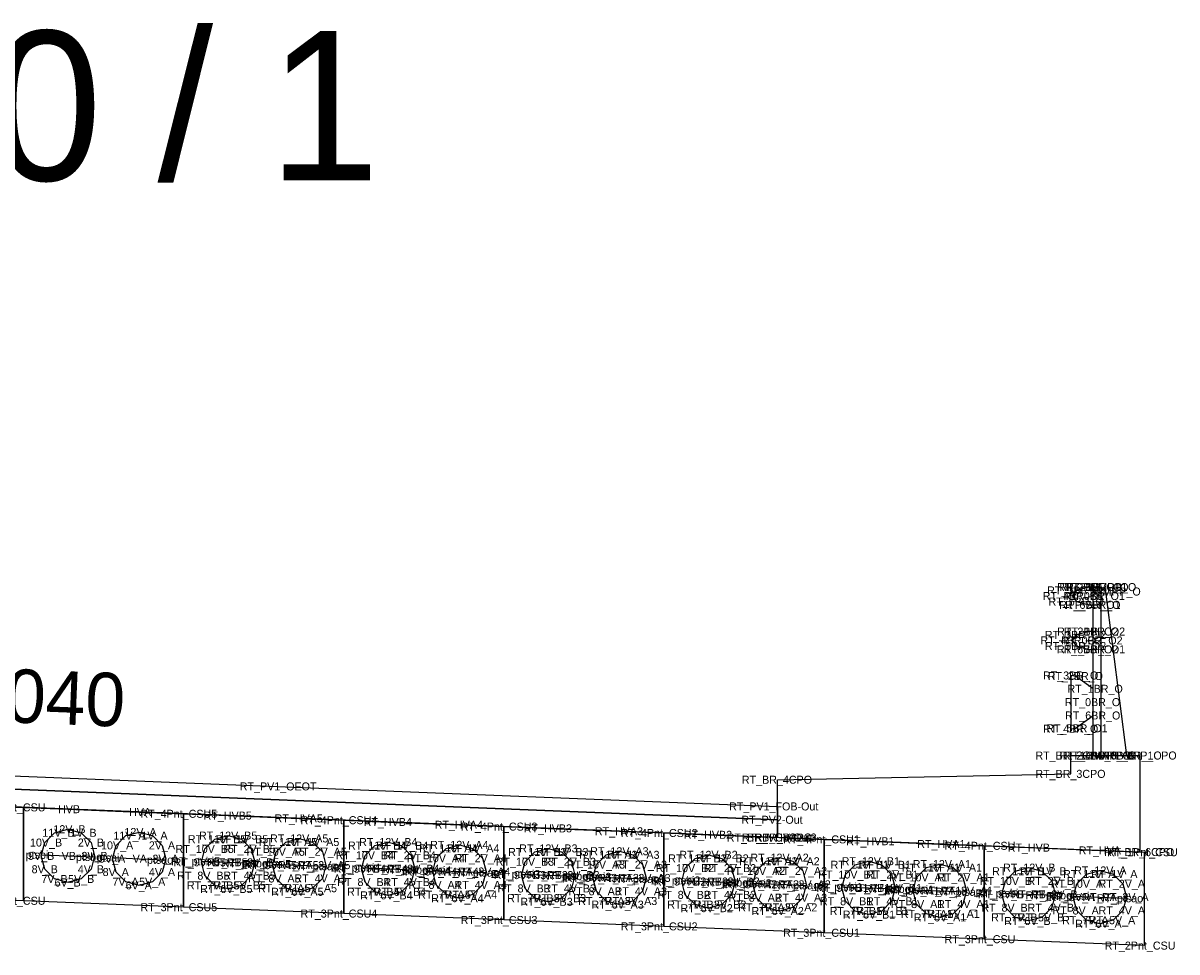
# Model space of a CAD drawing. Extents: x -26 to 1163, y -10 to 9537.
# Drawn here: x 84.24 to 105.86, y 6514.13 to 6531.53 of the extents above; entities that cross this region are included whole.
import ezdxf

# ---------------------------------------------------------------- set-up
doc = ezdxf.new("R2010")
doc.units = 0
for name, color, linetype in [('Exist Cross Section Cell', 7, 'Continuous'), ('Prop CMT Bridge Metal Rail', 7, 'Continuous'), ('Prop CMT Bridge Metal Rail Post', 7, 'Continuous'), ('Prop CMT Concrete Structures', 7, 'Continuous'), ('Prop CMT Corridor Surface Symbology Blue', 7, 'Continuous'), ('Prop CMT Pvmt Course 1', 7, 'Continuous'), ('Prop CMT Pvmt Course 2', 7, 'Continuous'), ('Prop XS SE Text', 7, 'Continuous'), ('Scratch_Level_0', 7, 'Continuous')]:
    doc.layers.add(name, color=color, linetype=linetype)

msp = doc.modelspace()

# ---------------------------------------------------------------- linework, layer by layer
at = {"layer": 'Prop CMT Bridge Metal Rail'}
for points in [[(104.293, 6520.965), (104.209, 6520.965), (103.98, 6520.902), (103.897, 6520.798)], [(104.293, 6520.798), (104.293, 6520.965)], [(103.897, 6520.798), (103.98, 6520.694), (104.209, 6520.632), (104.293, 6520.632)], [(104.293, 6520.632), (104.293, 6520.798)], [(104.293, 6520.132), (104.209, 6520.132), (103.98, 6520.069), (103.897, 6519.965)], [(103.897, 6519.965), (103.98, 6519.861), (104.209, 6519.798), (104.293, 6519.798)], [(104.293, 6519.965), (104.293, 6520.132)], [(104.293, 6519.798), (104.293, 6519.965)], [(104.293, 6519.059), (103.964, 6519.298), (103.876, 6519.309)], [(103.876, 6519.309), (103.876, 6518.309)], [(104.293, 6518.809), (104.293, 6519.059)], [(104.293, 6518.559), (104.293, 6518.809)], [(103.876, 6518.309), (103.964, 6518.319), (104.293, 6518.559)]]:
    msp.add_lwpolyline(points, dxfattribs=at)
at = {"layer": 'Prop CMT Bridge Metal Rail Post'}
for points in [[(104.293, 6517.809), (104.293, 6520.965)], [(104.293, 6520.965), (104.438, 6520.965)], [(104.438, 6520.965), (104.438, 6517.809)], [(104.438, 6520.965), (104.522, 6520.882), (104.918, 6517.809)]]:
    msp.add_lwpolyline(points, dxfattribs=at)
at = {"layer": 'Prop CMT Concrete Structures'}
for points in [[(98.375, 6516.272), (98.376, 6517.355), (103.875, 6517.465), (103.876, 6517.809), (105.166, 6517.809), (105.167, 6516)], [(81.25, 6516.957), (82.083, 6516.923), (83.417, 6516.87), (84.25, 6516.837)], [(84.25, 6516.837), (84.25, 6515.087)], [(84.25, 6516.837), (85.083, 6516.803), (86.417, 6516.75), (87.25, 6516.717)], [(84.25, 6515.087), (84.25, 6516.837)], [(87.25, 6516.717), (88.083, 6516.683), (89.417, 6516.63), (90.25, 6516.597)], [(87.25, 6514.967), (87.25, 6516.717)], [(87.25, 6516.717), (87.25, 6514.967)], [(90.25, 6516.597), (90.25, 6514.847)], [(90.25, 6516.597), (91.083, 6516.563), (92.417, 6516.51), (93.25, 6516.477)], [(90.25, 6514.847), (90.25, 6516.597)], [(93.25, 6516.477), (93.25, 6514.727)], [(93.25, 6516.477), (94.083, 6516.443), (95.417, 6516.39), (96.25, 6516.357)], [(93.25, 6514.727), (93.25, 6516.477)], [(84.583, 6515.928), (84.65, 6516.178), (84.833, 6516.361), (85.083, 6516.428)], [(85.083, 6516.428), (85.333, 6516.361), (85.516, 6516.178), (85.583, 6515.928)], [(85.917, 6515.875), (85.984, 6516.125), (86.167, 6516.308), (86.417, 6516.375)], [(86.417, 6516.375), (86.667, 6516.308), (86.85, 6516.125), (86.917, 6515.875)], [(87.583, 6515.808), (87.65, 6516.058), (87.833, 6516.241), (88.083, 6516.308)], [(88.083, 6516.308), (88.333, 6516.241), (88.516, 6516.058), (88.583, 6515.808)], [(96.25, 6516.357), (96.25, 6514.607)], [(96.25, 6516.357), (97.083, 6516.323), (98.417, 6516.27), (99.25, 6516.237)], [(96.25, 6514.607), (96.25, 6516.357)], [(105.167, 6516), (98.375, 6516.272)], [(88.917, 6515.755), (88.984, 6516.005), (89.167, 6516.188), (89.417, 6516.255)], [(89.417, 6516.255), (89.667, 6516.188), (89.85, 6516.005), (89.917, 6515.755)], [(90.583, 6515.688), (90.65, 6515.938), (90.833, 6516.121), (91.083, 6516.188)], [(91.083, 6516.188), (91.333, 6516.121), (91.516, 6515.938), (91.583, 6515.688)], [(91.917, 6515.635), (91.984, 6515.885), (92.167, 6516.068), (92.417, 6516.135)], [(92.417, 6516.135), (92.667, 6516.068), (92.85, 6515.885), (92.917, 6515.635)], [(93.583, 6515.568), (93.65, 6515.818), (93.833, 6516.001), (94.083, 6516.068)], [(94.083, 6516.068), (94.333, 6516.001), (94.516, 6515.818), (94.583, 6515.568)], [(99.25, 6516.237), (99.25, 6514.487)], [(99.25, 6516.237), (100.083, 6516.203), (101.417, 6516.15), (102.25, 6516.117)], [(99.25, 6514.487), (99.25, 6516.237)], [(102.25, 6516.117), (102.25, 6514.367)], [(102.25, 6516.117), (103.083, 6516.083), (104.417, 6516.03), (105.25, 6515.997)], [(102.25, 6514.367), (102.25, 6516.117)], [(85.583, 6515.928), (85.516, 6515.678), (85.333, 6515.495), (85.083, 6515.428), (84.833, 6515.495), (84.65, 6515.678), (84.583, 6515.928)], [(86.917, 6515.875), (86.85, 6515.625), (86.667, 6515.442), (86.417, 6515.375), (86.167, 6515.442), (85.984, 6515.625), (85.917, 6515.875)], [(94.917, 6515.515), (94.984, 6515.765), (95.167, 6515.948), (95.417, 6516.015)], [(95.417, 6516.015), (95.667, 6515.948), (95.85, 6515.765), (95.917, 6515.515)], [(96.583, 6515.448), (96.65, 6515.698), (96.833, 6515.881), (97.083, 6515.948)], [(97.083, 6515.948), (97.333, 6515.881), (97.516, 6515.698), (97.583, 6515.448)], [(97.917, 6515.395), (97.984, 6515.645), (98.167, 6515.828), (98.417, 6515.895)], [(98.417, 6515.895), (98.667, 6515.828), (98.85, 6515.645), (98.917, 6515.395)], [(99.583, 6515.328), (99.65, 6515.578), (99.833, 6515.761), (100.083, 6515.828)], [(100.083, 6515.828), (100.333, 6515.761), (100.516, 6515.578), (100.583, 6515.328)], [(105.25, 6515.997), (105.25, 6514.247)], [(88.583, 6515.808), (88.516, 6515.558), (88.333, 6515.375), (88.083, 6515.308), (87.833, 6515.375), (87.65, 6515.558), (87.583, 6515.808)], [(89.917, 6515.755), (89.85, 6515.505), (89.667, 6515.322), (89.417, 6515.255), (89.167, 6515.322), (88.984, 6515.505), (88.917, 6515.755)], [(91.583, 6515.688), (91.516, 6515.438), (91.333, 6515.255), (91.083, 6515.188), (90.833, 6515.255), (90.65, 6515.438), (90.583, 6515.688)], [(92.917, 6515.635), (92.85, 6515.385), (92.667, 6515.202), (92.417, 6515.135), (92.167, 6515.202), (91.984, 6515.385), (91.917, 6515.635)], [(100.917, 6515.275), (100.984, 6515.525), (101.167, 6515.708), (101.417, 6515.775)], [(101.417, 6515.775), (101.667, 6515.708), (101.85, 6515.525), (101.917, 6515.275)], [(102.583, 6515.208), (102.65, 6515.458), (102.833, 6515.641), (103.083, 6515.708)], [(103.083, 6515.708), (103.333, 6515.641), (103.516, 6515.458), (103.583, 6515.208)], [(103.917, 6515.155), (103.984, 6515.405), (104.167, 6515.588), (104.417, 6515.655)], [(104.417, 6515.655), (104.667, 6515.588), (104.85, 6515.405), (104.917, 6515.155)], [(94.583, 6515.568), (94.516, 6515.318), (94.333, 6515.135), (94.083, 6515.068), (93.833, 6515.135), (93.65, 6515.318), (93.583, 6515.568)], [(95.917, 6515.515), (95.85, 6515.265), (95.667, 6515.082), (95.417, 6515.015), (95.167, 6515.082), (94.984, 6515.265), (94.917, 6515.515)], [(97.583, 6515.448), (97.516, 6515.198), (97.333, 6515.015), (97.083, 6514.948), (96.833, 6515.015), (96.65, 6515.198), (96.583, 6515.448)], [(84.25, 6515.087), (81.25, 6515.207)], [(98.917, 6515.395), (98.85, 6515.145), (98.667, 6514.962), (98.417, 6514.895), (98.167, 6514.962), (97.984, 6515.145), (97.917, 6515.395)], [(100.583, 6515.328), (100.516, 6515.078), (100.333, 6514.895), (100.083, 6514.828), (99.833, 6514.895), (99.65, 6515.078), (99.583, 6515.328)], [(101.917, 6515.275), (101.85, 6515.025), (101.667, 6514.842), (101.417, 6514.775), (101.167, 6514.842), (100.984, 6515.025), (100.917, 6515.275)], [(103.583, 6515.208), (103.516, 6514.958), (103.333, 6514.775), (103.083, 6514.708), (102.833, 6514.775), (102.65, 6514.958), (102.583, 6515.208)], [(87.25, 6514.967), (84.25, 6515.087)], [(90.25, 6514.847), (87.25, 6514.967)], [(104.917, 6515.155), (104.85, 6514.905), (104.667, 6514.722), (104.417, 6514.655), (104.167, 6514.722), (103.984, 6514.905), (103.917, 6515.155)], [(93.25, 6514.727), (90.25, 6514.847)], [(96.25, 6514.607), (93.25, 6514.727)], [(99.25, 6514.487), (96.25, 6514.607)], [(102.25, 6514.367), (99.25, 6514.487)], [(105.25, 6514.247), (102.25, 6514.367)]]:
    msp.add_lwpolyline(points, dxfattribs=at)
at = {"layer": 'Prop CMT Corridor Surface Symbology Blue'}
for points in [[(84.593, 6515.948), (85.083, 6515.928), (85.573, 6515.909)], [(85.927, 6515.895), (86.417, 6515.875), (86.907, 6515.855)], [(87.593, 6515.828), (88.083, 6515.808), (88.573, 6515.789)], [(88.927, 6515.775), (89.417, 6515.755), (89.907, 6515.735)], [(90.593, 6515.708), (91.083, 6515.688), (91.573, 6515.669)], [(91.927, 6515.655), (92.417, 6515.635), (92.907, 6515.615)], [(93.593, 6515.588), (94.083, 6515.568), (94.573, 6515.549)], [(94.927, 6515.535), (95.417, 6515.515), (95.907, 6515.495)], [(96.593, 6515.468), (97.083, 6515.448), (97.573, 6515.429)], [(97.927, 6515.415), (98.417, 6515.395), (98.907, 6515.375)], [(99.593, 6515.348), (100.083, 6515.328), (100.573, 6515.309)], [(100.927, 6515.295), (101.417, 6515.275), (101.907, 6515.255)], [(102.593, 6515.228), (103.083, 6515.208), (103.573, 6515.189)], [(103.927, 6515.175), (104.417, 6515.155), (104.907, 6515.135)]]:
    msp.add_lwpolyline(points, dxfattribs=at)
at = {"layer": 'Prop CMT Pvmt Course 1'}
for points in [[(80, 6517.59), (89, 6517.23), (98.376, 6516.855)], [(98.376, 6516.855), (98.376, 6516.605), (80, 6517.34)]]:
    msp.add_lwpolyline(points, dxfattribs=at)
at = {"layer": 'Prop CMT Pvmt Course 2'}
for points in [[(80, 6517.34), (98.376, 6516.605)], [(98.376, 6516.605), (98.375, 6516.272), (80, 6517.007)]]:
    msp.add_lwpolyline(points, dxfattribs=at)

# ---------------------------------------------------------------- texts
at = {"layer": 'Exist Cross Section Cell'}
msp.add_text('16+50.00 / 1', height=2.8, dxfattribs=at).set_placement((70, 6528.585))
at = {"layer": 'Prop XS SE Text'}
msp.add_text('0.040', height=1, rotation=357.7094, dxfattribs=at).set_placement((82.791, 6518.479))
at = {"layer": 'Scratch_Level_0'}
for s, p in [('RT_2BMRP_O', (103.617, 6520.89)), ('RT_2BR_O1', (103.66, 6520.89)), ('RT_3BMRP_O', (103.763, 6520.89)), ('RT_1BR_O1', (103.786, 6520.89)), ('RT_4BR_O1', (103.348, 6520.723)), ('RT_3BR_O1', (103.431, 6520.827)), ('RT_0BR_O1', (103.738, 6520.723)), ('RT_5BMRP_O', (103.846, 6520.807)), ('RT_5BR_O', (103.456, 6520.619)), ('RT_6BR_O1', (103.657, 6520.557)), ('RT_7BR_O', (103.768, 6520.557)), ('RT_2BR_O2', (103.618, 6520.057)), ('RT_1BR_O2', (103.743, 6520.057)), ('RT_4BR_O2', (103.305, 6519.89)), ('RT_3BR_O2', (103.388, 6519.994)), ('RT_5BR_O2', (103.388, 6519.786)), ('RT_0BR_O2', (103.695, 6519.89)), ('RT_6BR_O2', (103.614, 6519.723)), ('RT_7BR_O1', (103.743, 6519.723)), ('RT_3BR_O', (103.352, 6519.234)), ('RT_2BR_O', (103.44, 6519.223)), ('RT_1BR_O', (103.811, 6518.984)), ('RT_0BR_O', (103.762, 6518.734)), ('RT_6BR_O', (103.765, 6518.484)), ('RT_4BR_O', (103.352, 6518.234)), ('RT_5BR_O1', (103.415, 6518.244)), ('RT_BR_2CPO', (103.21, 6517.734)), ('RT_1BMRP_O', (103.66, 6517.734)), ('RT_4BMRP_O', (103.763, 6517.734)), ('RT_6BMRP_O', (104.239, 6517.734)), ('RT_BR_1CPO', (104.542, 6517.734)), ('RT_BR_4CPO', (97.71, 6517.28)), ('RT_BR_3CPO', (103.209, 6517.39)), ('RT_PV1_OEOT', (88.302, 6517.155)), ('4Pnt_CSU', (83.714, 6516.762)), ('RT_PV1_FOB-Out', (97.471, 6516.78)), ('HVB', (84.897, 6516.728)), ('HVA', (86.228, 6516.675)), ('RT_4Pnt_CSU5', (86.441, 6516.642)), ('RT_HVB5', (87.624, 6516.608)), ('RT_HVA5', (88.955, 6516.555)), ('12V_B', (84.81, 6516.353)), ('RT_4Pnt_CSU4', (89.441, 6516.522)), ('RT_HVB4', (90.624, 6516.488)), ('RT_HVA4', (91.955, 6516.435)), ('RT_4Pnt_CSU3', (92.441, 6516.402)), ('RT_HVB3', (93.624, 6516.368)), ('RT_PV2-Out', (97.701, 6516.53)), ('11V_B', (84.603, 6516.286)), ('1V_B', (85.128, 6516.286)), ('11V_A', (85.934, 6516.233)), ('12V_A', (86.141, 6516.3)), ('1V_A', (86.459, 6516.233)), ('RT_11V_B5', (87.33, 6516.166)), ('RT_12V_B5', (87.538, 6516.233)), ('RT_1V_B5', (87.855, 6516.166)), ('RT_11V_A5', (88.661, 6516.113)), ('RT_12V_A5', (88.869, 6516.18)), ('RT_1V_A5', (89.186, 6516.113)), ('RT_12V_B4', (90.538, 6516.113)), ('RT_HVA3', (94.955, 6516.315)), ('RT_4Pnt_CSU2', (95.441, 6516.282)), ('RT_HVB2', (96.624, 6516.248)), ('RT_BR_VCB-Out3', (97.427, 6516.197)), ('RT_BR_5CPO', (97.709, 6516.197)), ('RT_HVA2', (97.955, 6516.195)), ('RT_4Pnt_CSU1', (98.483, 6516.162)), ('RT_HVB1', (99.666, 6516.128)), ('10V_B', (84.372, 6516.103)), ('2V_B', (85.268, 6516.103)), ('10V_A', (85.703, 6516.05)), ('2V_A', (86.599, 6516.05)), ('RT_10V_B5', (87.099, 6515.983)), ('RT_2V_B5', (87.995, 6515.983)), ('RT_10V_A5', (88.43, 6515.93)), ('RT_2V_A5', (89.326, 6515.93)), ('RT_11V_B4', (90.33, 6516.046)), ('RT_1V_B4', (90.855, 6516.046)), ('RT_11V_A4', (91.661, 6515.993)), ('RT_12V_A4', (91.869, 6516.06)), ('RT_1V_A4', (92.186, 6515.993)), ('RT_11V_B3', (93.33, 6515.926)), ('RT_12V_B3', (93.538, 6515.993)), ('RT_1V_B3', (93.855, 6515.926)), ('RT_12V_A3', (94.869, 6515.94)), ('RT_HVA1', (100.997, 6516.075)), ('RT_4Pnt_CSU', (101.508, 6516.042)), ('RT_HVB', (102.691, 6516.008)), ('RT_HVA', (104.022, 6515.955)), ('RT_BR_6CPO', (104.497, 6515.925)), ('RT_1Pnt_CSU', (104.551, 6515.922)), ('ptsbi', (84.292, 6515.873)), ('9V_B', (84.335, 6515.853)), ('VB', (84.964, 6515.853)), ('ptsbo', (85.232, 6515.834)), ('3V_B', (85.335, 6515.853)), ('ptsai', (85.624, 6515.82)), ('9V_A', (85.666, 6515.8)), ('VA', (86.295, 6515.8)), ('ptsao', (86.564, 6515.78)), ('3V_A', (86.666, 6515.8)), ('RT_ptsbi5', (87.019, 6515.753)), ('RT_9V_B5', (87.062, 6515.733)), ('RT_VB5', (87.691, 6515.733)), ('RT_ptsbo5', (87.959, 6515.714)), ('RT_3V_B5', (88.062, 6515.733)), ('RT_ptsai5', (88.351, 6515.7)), ('RT_9V_A5', (88.393, 6515.68)), ('RT_VA5', (89.022, 6515.68)), ('RT_3V_A5', (89.393, 6515.68)), ('RT_10V_B4', (90.099, 6515.863)), ('RT_2V_B4', (90.995, 6515.863)), ('RT_10V_A4', (91.43, 6515.81)), ('RT_2V_A4', (92.326, 6515.81)), ('RT_10V_B3', (93.099, 6515.743)), ('RT_2V_B3', (93.995, 6515.743)), ('RT_10V_A3', (94.43, 6515.69)), ('RT_11V_A3', (94.661, 6515.873)), ('RT_1V_A3', (95.186, 6515.873)), ('RT_2V_A3', (95.326, 6515.69)), ('RT_11V_B2', (96.33, 6515.806)), ('RT_12V_B2', (96.538, 6515.873)), ('RT_1V_B2', (96.855, 6515.806)), ('RT_11V_A2', (97.661, 6515.753)), ('RT_12V_A2', (97.869, 6515.82)), ('RT_1V_A2', (98.186, 6515.753)), ('RT_11V_B1', (99.373, 6515.686)), ('RT_12V_B1', (99.58, 6515.753)), ('RT_1V_B1', (99.898, 6515.686)), ('RT_12V_A1', (100.911, 6515.7)), ('8V_B', (84.402, 6515.603)), ('4V_B', (85.268, 6515.603)), ('8V_A', (85.733, 6515.55)), ('4V_A', (86.599, 6515.55)), ('RT_8V_B5', (87.129, 6515.483)), ('RT_4V_B5', (87.995, 6515.483)), ('RT_ptsao5', (89.291, 6515.66)), ('RT_ptsbi4', (90.019, 6515.633)), ('RT_9V_B4', (90.062, 6515.613)), ('RT_VB4', (90.691, 6515.613)), ('RT_ptsbo4', (90.959, 6515.594)), ('RT_3V_B4', (91.062, 6515.613)), ('RT_ptsai4', (91.351, 6515.58)), ('RT_9V_A4', (91.393, 6515.56)), ('RT_VA4', (92.022, 6515.56)), ('RT_ptsao4', (92.291, 6515.54)), ('RT_3V_A4', (92.393, 6515.56)), ('RT_ptsbi3', (93.019, 6515.513)), ('RT_9V_B3', (93.062, 6515.493)), ('RT_VB3', (93.691, 6515.493)), ('RT_ptsbo3', (93.959, 6515.474)), ('RT_3V_B3', (94.062, 6515.493)), ('RT_ptsai3', (94.351, 6515.46)), ('RT_10V_B2', (96.099, 6515.623)), ('RT_2V_B2', (96.995, 6515.623)), ('RT_10V_A2', (97.43, 6515.57)), ('RT_2V_A2', (98.326, 6515.57)), ('RT_10V_B1', (99.141, 6515.503)), ('RT_2V_B1', (100.038, 6515.503)), ('RT_11V_A1', (100.704, 6515.633)), ('RT_1V_A1', (101.228, 6515.633)), ('RT_11V_B', (102.398, 6515.566)), ('RT_12V_B', (102.605, 6515.633)), ('RT_1V_B', (102.922, 6515.566)), ('RT_11V_A', (103.728, 6515.513)), ('RT_12V_A', (103.936, 6515.58)), ('RT_1V_A', (104.253, 6515.513)), ('7V_B', (84.585, 6515.42)), ('6V_B', (84.832, 6515.353)), ('5V_B', (85.085, 6515.42)), ('7V_A', (85.916, 6515.367)), ('6V_A', (86.163, 6515.3)), ('5V_A', (86.416, 6515.367)), ('RT_7V_B5', (87.312, 6515.3)), ('RT_5V_B5', (87.812, 6515.3)), ('RT_8V_A5', (88.46, 6515.43)), ('RT_7V_A5', (88.643, 6515.247)), ('RT_5V_A5', (89.143, 6515.247)), ('RT_4V_A5', (89.326, 6515.43)), ('RT_8V_B4', (90.129, 6515.363)), ('RT_4V_B4', (90.995, 6515.363)), ('RT_8V_A4', (91.46, 6515.31)), ('RT_4V_A4', (92.326, 6515.31)), ('RT_8V_B3', (93.129, 6515.243)), ('RT_4V_B3', (93.995, 6515.243)), ('RT_9V_A3', (94.393, 6515.44)), ('RT_VA3', (95.022, 6515.44)), ('RT_ptsao3', (95.291, 6515.42)), ('RT_3V_A3', (95.393, 6515.44)), ('RT_ptsbi2', (96.019, 6515.393)), ('RT_9V_B2', (96.062, 6515.373)), ('RT_VB2', (96.691, 6515.373)), ('RT_ptsbo2', (96.959, 6515.354)), ('RT_3V_B2', (97.062, 6515.373)), ('RT_ptsai2', (97.351, 6515.34)), ('RT_9V_A2', (97.393, 6515.32)), ('RT_VA2', (98.022, 6515.32)), ('RT_ptsao2', (98.291, 6515.3)), ('RT_3V_A2', (98.393, 6515.32)), ('RT_ptsbi1', (99.062, 6515.273)), ('RT_9V_B1', (99.105, 6515.253)), ('RT_VB1', (99.734, 6515.253)), ('RT_3V_B1', (100.105, 6515.253)), ('RT_10V_A1', (100.472, 6515.45)), ('RT_2V_A1', (101.369, 6515.45)), ('RT_10V_B', (102.166, 6515.383)), ('RT_2V_B', (103.063, 6515.383)), ('RT_10V_A', (103.497, 6515.33)), ('RT_2V_A', (104.394, 6515.33)), ('RT_6V_B5', (87.559, 6515.233)), ('RT_6V_A5', (88.89, 6515.18)), ('RT_7V_B4', (90.312, 6515.18)), ('RT_6V_B4', (90.559, 6515.113)), ('RT_5V_B4', (90.812, 6515.18)), ('RT_7V_A4', (91.643, 6515.127)), ('RT_6V_A4', (91.89, 6515.06)), ('RT_5V_A4', (92.143, 6515.127)), ('RT_7V_B3', (93.312, 6515.06)), ('RT_5V_B3', (93.812, 6515.06)), ('RT_8V_A3', (94.46, 6515.19)), ('RT_4V_A3', (95.326, 6515.19)), ('RT_8V_B2', (96.129, 6515.123)), ('RT_4V_B2', (96.995, 6515.123)), ('RT_8V_A2', (97.46, 6515.07)), ('RT_4V_A2', (98.326, 6515.07)), ('RT_ptsbo1', (100.002, 6515.234)), ('RT_ptsai1', (100.394, 6515.22)), ('RT_9V_A1', (100.436, 6515.2)), ('RT_VA1', (101.065, 6515.2)), ('RT_ptsao1', (101.334, 6515.18)), ('RT_3V_A1', (101.436, 6515.2)), ('RT_ptsbi', (102.087, 6515.153)), ('RT_9V_B', (102.13, 6515.133)), ('RT_VB', (102.759, 6515.133)), ('RT_ptsbo', (103.026, 6515.114)), ('RT_3V_B', (103.13, 6515.133)), ('RT_ptsai', (103.419, 6515.1)), ('RT_9V_A', (103.461, 6515.08)), ('RT_VA', (104.09, 6515.08)), ('RT_ptsao', (104.359, 6515.06)), ('RT_3V_A', (104.461, 6515.08)), ('3Pnt_CSU', (83.714, 6515.012)), ('RT_3Pnt_CSU5', (86.441, 6514.892)), ('RT_6V_B3', (93.559, 6514.993)), ('RT_7V_A3', (94.643, 6515.007)), ('RT_6V_A3', (94.89, 6514.94)), ('RT_5V_A3', (95.143, 6515.007)), ('RT_7V_B2', (96.312, 6514.94)), ('RT_6V_B2', (96.559, 6514.873)), ('RT_5V_B2', (96.812, 6514.94)), ('RT_7V_A2', (97.643, 6514.887)), ('RT_6V_A2', (97.89, 6514.82)), ('RT_5V_A2', (98.143, 6514.887)), ('RT_8V_B1', (99.172, 6515.003)), ('RT_7V_B1', (99.355, 6514.82)), ('RT_5V_B1', (99.855, 6514.82)), ('RT_4V_B1', (100.038, 6515.003)), ('RT_8V_A1', (100.503, 6514.95)), ('RT_4V_A1', (101.369, 6514.95)), ('RT_8V_B', (102.197, 6514.883)), ('RT_4V_B', (103.063, 6514.883)), ('RT_8V_A', (103.528, 6514.83)), ('RT_4V_A', (104.394, 6514.83)), ('RT_3Pnt_CSU4', (89.441, 6514.772)), ('RT_3Pnt_CSU3', (92.441, 6514.652)), ('RT_6V_B1', (99.601, 6514.753)), ('RT_7V_A1', (100.686, 6514.767)), ('RT_6V_A1', (100.932, 6514.7)), ('RT_5V_A1', (101.186, 6514.767)), ('RT_7V_B', (102.38, 6514.7)), ('RT_6V_B', (102.626, 6514.633)), ('RT_5V_B', (102.88, 6514.7)), ('RT_7V_A', (103.711, 6514.647)), ('RT_5V_A', (104.211, 6514.647)), ('RT_3Pnt_CSU2', (95.441, 6514.532)), ('RT_3Pnt_CSU1', (98.483, 6514.412)), ('RT_6V_A', (103.957, 6514.58)), ('RT_3Pnt_CSU', (101.508, 6514.292)), ('RT_2Pnt_CSU', (104.508, 6514.172))]:
    msp.add_text(s, height=0.15, dxfattribs=at).set_placement(p)

doc.saveas('drawing.dxf')
